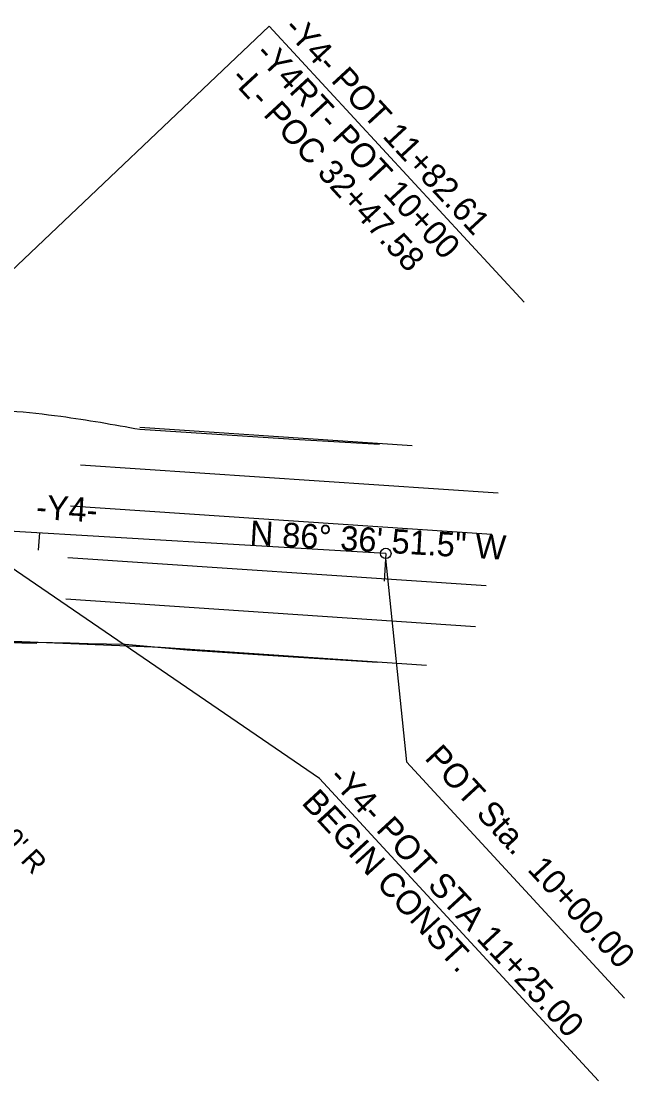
# Model space of a CAD drawing. Extents: x 1702862 to 1704514, y 793768 to 796215.
# Drawn here: x 1704063.5 to 1704240, y 794037 to 794342.3 of the extents above; entities that cross this region are included whole.
import ezdxf

# ---------------------------------------------------------------- set-up
doc = ezdxf.new("R2010")
doc.units = 0
for name, color, linetype in [('Exist Horizontal Alignment', 7, 'Continuous'), ('Old_Level_3', 7, 'Continuous'), ('Prop Dimension Text', 7, 'Continuous'), ('Prop DSN Text', 7, 'Continuous'), ('Prop Horizontal Alignment', 7, 'Continuous'), ('Prop Horizontal Alignment Direction Label', 7, 'Continuous'), ('Prop Horizontal Alignment Station Label', 7, 'Continuous'), ('Prop Horizontal Alignment Tick Large', 7, 'Continuous'), ('Prop Horizontal Alignment Tick Small', 7, 'Continuous'), ('Prop Lane Lines', 7, 'Continuous'), ('Prop Leader Line Medium', 7, 'Continuous')]:
    doc.layers.add(name, color=color, linetype=linetype)

msp = doc.modelspace()

# ---------------------------------------------------------------- linework, layer by layer
at = {"layer": 'Exist Horizontal Alignment'}
msp.add_line((1704168.58, 794188.93), (1704163.59, 794189.23), dxfattribs=at)
at = {"layer": 'Old_Level_3'}
for points in [[(1704097.71, 794224.72), (1704142.07, 794221.88), (1704166.72, 794220.42)], [(1704166.22, 794157.53), (1704141.86, 794159.07), (1704111.38, 794161.02), (1704093.48, 794162.67)]]:
    msp.add_lwpolyline(points, dxfattribs=at)
for points in [[(1704045.87, 794231.21), (1704074.98, 794228.45), (1704097.71, 794224.72)], [(1704093.48, 794162.67), (1704041.88, 794163.83), (1704068.07, 794163.09)]]:
    msp.add_spline(points, degree=3, dxfattribs=at)
at = {"layer": 'Prop Horizontal Alignment'}
for p, q in [((1704163.59, 794189.23), (1703986.29, 794199.72)), ((1704168.58, 794188.93), (1704163.59, 794189.23))]:
    msp.add_line(p, q, dxfattribs=at)
at = {"layer": 'Prop Horizontal Alignment Station Label'}
for p, q in [((1703986.29, 794199.72), (1704135, 794340.88)), ((1704135, 794340.88), (1704208.42, 794261.33)), ((1704168.49, 794187.44), (1704174.54, 794128.85)), ((1704174.54, 794128.85), (1704237.37, 794060.78))]:
    msp.add_line(p, q, dxfattribs=at)
msp.add_circle((1704168.58, 794188.93), 1.5, dxfattribs=at)
at = {"layer": 'Prop Horizontal Alignment Tick Large'}
msp.add_line((1704168.58, 794188.93), (1704168.11, 794180.95), dxfattribs=at)
at = {"layer": 'Prop Horizontal Alignment Tick Small'}
msp.add_line((1704068.76, 794194.84), (1704068.46, 794189.85), dxfattribs=at)
at = {"layer": 'Prop Lane Lines'}
for p, q in [((1704097.73, 794225.32), (1704176.21, 794220.05)), ((1704080.63, 794214.44), (1704200.97, 794206.35)), ((1704077.77, 794202.61), (1704199.13, 794194.45)), ((1704076.95, 794187.8), (1704197.48, 794179.69)), ((1704076.4, 794175.81), (1704194.47, 794167.86)), ((1704048.71, 794164.14), (1704103.67, 794161.95)), ((1704103.67, 794161.95), (1704180.27, 794156.79))]:
    msp.add_line(p, q, dxfattribs=at)
at = {"layer": 'Prop Leader Line Medium'}
for q in [(1704043.8, 794196.32), (1704229.89, 794036.99)]:
    msp.add_line((1704149.5, 794124.08), q, dxfattribs=at)

# ---------------------------------------------------------------- texts
at = {"layer": 'Prop Dimension Text'}
msp.add_text("40' R", height=6, rotation=312.7091, dxfattribs=at).set_placement((1704054.49, 794109.65))
at = {"layer": 'Prop DSN Text'}
for s, p in [('-Y4- POT STA 11+25.00', (1704151.76, 794124.07)), ('BEGIN CONST.', (1704144.04, 794116.95))]:
    msp.add_text(s, height=7, rotation=312.7091, dxfattribs=at).set_placement(p)
at = {"layer": 'Prop Horizontal Alignment Direction Label'}
for s, p in [('-Y4-', (1704067.67, 794198.9)), ('N 86%%d 36\' 51.5" W', (1704129.24, 794191.46))]:
    msp.add_text(s, height=7, rotation=356.6143, dxfattribs=at).set_placement(p)
at = {"layer": 'Prop Horizontal Alignment Station Label'}
for s, p in [('-Y4- POT 11+82.61', (1704138.79, 794339.98)), ('-Y4RT- POT 10+00', (1704130.56, 794332.63)), ('-L- POC 32+47.58', (1704123.51, 794325.57)), ('POT Sta.  10+00.00', (1704179.51, 794129.8))]:
    msp.add_text(s, height=7, rotation=312.7091, dxfattribs=at).set_placement(p)

doc.saveas('drawing.dxf')
